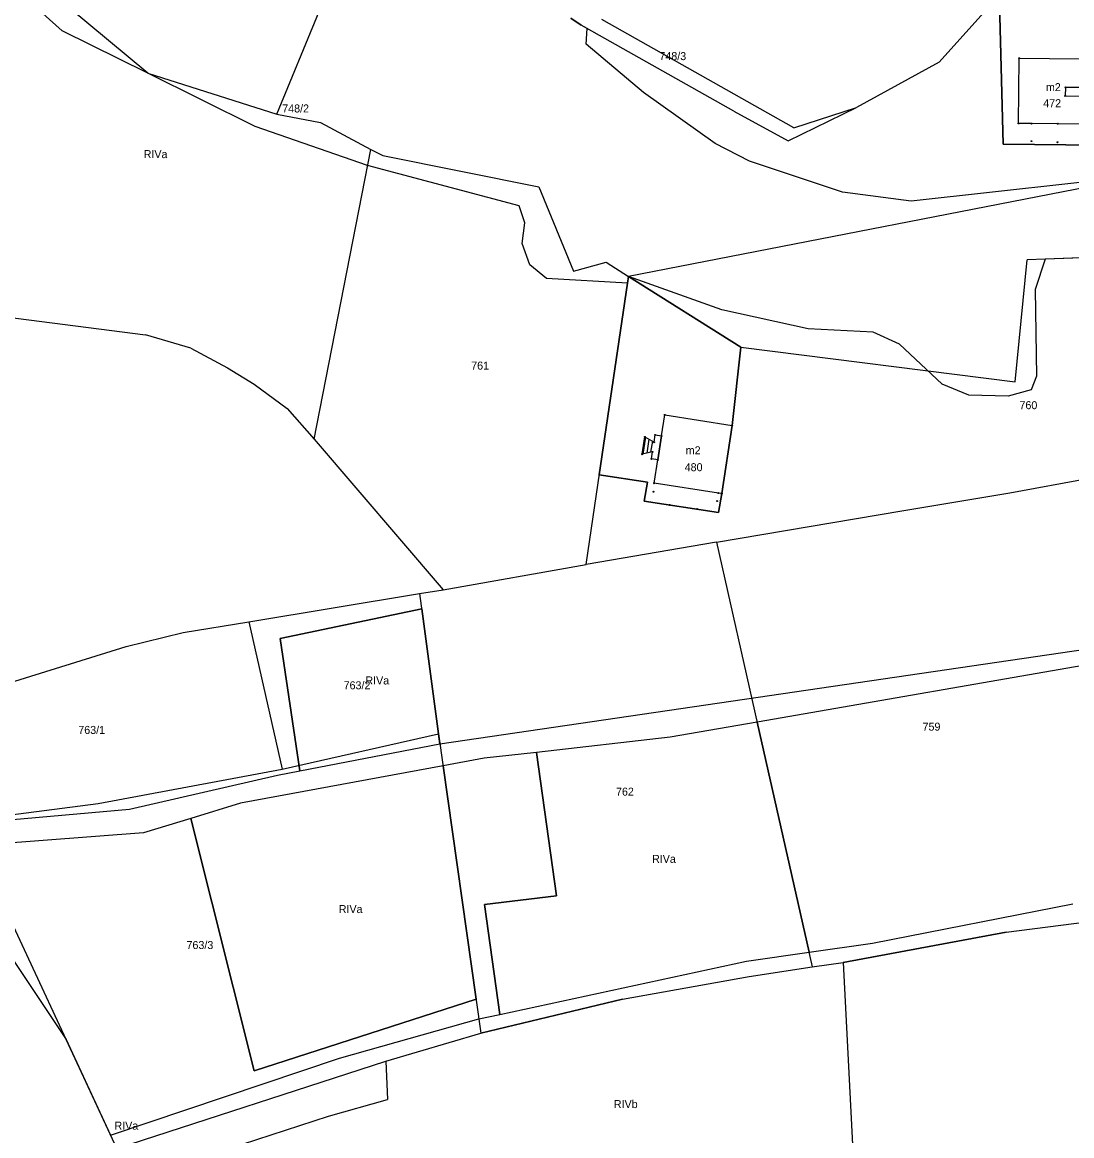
# Model space of a CAD drawing. Extents: x 7498273 to 7499989, y 5499795 to 5500810.
# Drawn here: x 7498697.1 to 7498893.9, y 5500193.5 to 5500402.3 of the extents above; entities that cross this region are included whole.
import ezdxf

# ---------------------------------------------------------------- set-up
doc = ezdxf.new("R2010")
doc.units = 0
for name, color, linetype in [('209-oznaczenie konturu klasyfikacyjnego', 7, 'Continuous'), ('211-numer działki ewidencyjnej', 7, 'Continuous'), ('217-kontur klasyfikacyjny', 7, 'Continuous'), ('218-kontur użytku gruntowego', 7, 'Continuous'), ('219-działka ewidencyjna', 7, 'Continuous'), ('312-budynek ewidencyjny', 7, 'Continuous'), ('312-oznaczenie budynku ewidencyjnego', 7, 'Continuous'), ('312-oznaczenie budynku ewidencyjnego-Atr117', 7, 'Continuous'), ('352-schody', 7, 'Continuous'), ('Punkt budynku', 7, 'Continuous')]:
    doc.layers.add(name, color=color, linetype=linetype)

# ---------------------------------------------------------------- blocks, each defined once
blk = doc.blocks.new('PUNKTBUD')
blk.add_circle((0, 0), 0.09)

msp = doc.modelspace()

# ---------------------------------------------------------------- linework, layer by layer
at = {"layer": '217-kontur klasyfikacyjny'}
for points in [[(7498704.59, 5500400.68), (7498692.57, 5500411.41)], [(7498881.05, 5500379.45), (7498880.27, 5500408.33)], [(7498801.93, 5500401.77), (7498799.95, 5500403.05)], [(7498720.65, 5500392.72), (7498704.59, 5500400.68)], [(7498803.06, 5500401.13), (7498801.93, 5500401.77)], [(7498802.86, 5500398.17), (7498803.06, 5500401.13)], [(7498813.6, 5500389.12), (7498802.86, 5500398.17)], [(7498740.78, 5500382.73), (7498720.65, 5500392.72)], [(7498827.05, 5500379.57), (7498813.6, 5500389.12)], [(7498761.84, 5500375.41), (7498740.78, 5500382.73)], [(7498833.45, 5500376.26), (7498827.05, 5500379.57)], [(7498898.64, 5500379.25), (7498881.05, 5500379.45)], [(7498850.89, 5500370.41), (7498833.45, 5500376.26)], [(7498790.29, 5500367.88), (7498761.84, 5500375.41)], [(7498908.98, 5500373.76), (7498863.81, 5500368.75)], [(7498863.81, 5500368.75), (7498850.89, 5500370.41)], [(7498791.33, 5500364.65), (7498790.29, 5500367.88)], [(7498790.87, 5500360.78), (7498791.33, 5500364.65)], [(7498792.29, 5500356.82), (7498790.87, 5500360.78)], [(7498795.4, 5500354.27), (7498792.29, 5500356.82)], [(7498888.92, 5500357.87), (7498887.03, 5500352.2)], [(7498902.28, 5500358.34), (7498888.92, 5500357.87)], [(7498810.57, 5500353.35), (7498810.76, 5500354.62)], [(7498828.29, 5500348.37), (7498810.76, 5500354.62)], [(7498810.76, 5500354.62), (7498831.84, 5500341.35)], [(7498810.57, 5500353.35), (7498795.4, 5500354.27)], [(7498805.31, 5500317.44), (7498810.57, 5500353.35)], [(7498887.03, 5500352.2), (7498887.26, 5500335.93)], [(7498844.5, 5500344.8), (7498828.29, 5500348.37)], [(7498856.66, 5500344.15), (7498844.5, 5500344.8)], [(7498861.61, 5500341.95), (7498856.66, 5500344.15)], [(7498831.84, 5500341.35), (7498830.25, 5500326.7)], [(7498869.61, 5500334.46), (7498861.61, 5500341.95)], [(7498887.26, 5500335.93), (7498886.31, 5500333.35)], [(7498874.57, 5500332.39), (7498869.61, 5500334.46)], [(7498881.95, 5500332.19), (7498874.57, 5500332.39)], [(7498886.31, 5500333.35), (7498881.95, 5500332.19)], [(7498830.25, 5500326.7), (7498828.26, 5500313.9)], [(7498814.33, 5500316.05), (7498805.31, 5500317.44)], [(7498813.71, 5500312.47), (7498814.33, 5500316.05)], [(7498828.26, 5500313.9), (7498827.64, 5500310.37)], [(7498827.64, 5500310.37), (7498813.71, 5500312.47)], [(7498745.47, 5500286.76), (7498772.01, 5500292.33)], [(7498772.01, 5500292.33), (7498775.16, 5500268.89)], [(7498775.42, 5500267.02), (7498925.02, 5500288.93)], [(7498749.18, 5500261.92), (7498745.47, 5500286.76)], [(7498900.34, 5500282.45), (7498834.9, 5500271.08)], [(7498834.9, 5500271.08), (7498818.61, 5500268.25)], [(7498844.63, 5500227.91), (7498834.9, 5500271.08)], [(7498749.18, 5500261.92), (7498775.42, 5500267.02)], [(7498775.16, 5500268.89), (7498775.42, 5500267.02)], [(7498818.61, 5500268.25), (7498793.52, 5500265.39)], [(7498793.52, 5500265.39), (7498783.73, 5500264.28)], [(7498797.28, 5500238.51), (7498793.52, 5500265.39)], [(7498776.01, 5500262.86), (7498738.05, 5500255.86)], [(7498783.73, 5500264.28), (7498776.01, 5500262.86)], [(7498776.01, 5500262.86), (7498782.2, 5500219.14)], [(7498717.23, 5500254.76), (7498745, 5500261.11)], [(7498745, 5500261.11), (7498749.18, 5500261.92)], [(7498672.71, 5500250.81), (7498717.23, 5500254.76)], [(7498738.05, 5500255.86), (7498728.72, 5500253)], [(7498728.72, 5500253), (7498719.84, 5500250.28)], [(7498740.6, 5500205.66), (7498728.72, 5500253)], [(7498719.84, 5500250.28), (7498682.16, 5500247.41)], [(7498783.76, 5500236.86), (7498797.28, 5500238.51)], [(7498786.64, 5500216.26), (7498783.76, 5500236.86)], [(7498856.53, 5500229.62), (7498894.08, 5500236.97)], [(7498881.57, 5500231.71), (7498904.55, 5500234.65)], [(7498851.03, 5500225.97), (7498881.57, 5500231.71)], [(7498844.63, 5500227.91), (7498856.53, 5500229.62)], [(7498694.7, 5500227.52), (7498705.34, 5500211.55)], [(7498832.92, 5500226.22), (7498844.63, 5500227.91)], [(7498786.64, 5500216.26), (7498832.92, 5500226.22)], [(7498833.4, 5500223.35), (7498845.25, 5500225.16)], [(7498845.25, 5500225.16), (7498851.03, 5500225.97)], [(7498809.65, 5500219.11), (7498833.4, 5500223.35)], [(7498782.2, 5500219.14), (7498740.6, 5500205.66)], [(7498783.11, 5500212.72), (7498809.65, 5500219.11)], [(7498756.62, 5500208.05), (7498782.73, 5500215.42)], [(7498782.73, 5500215.42), (7498786.64, 5500216.26)], [(7498765.31, 5500207.49), (7498783.11, 5500212.72)], [(7498705.34, 5500211.55), (7498713.67, 5500193.65)], [(7498713.67, 5500193.65), (7498756.62, 5500208.05)], [(7498714.83, 5500191.15), (7498765.31, 5500207.49)]]:
    msp.add_lwpolyline(points, dxfattribs=at)
at = {"layer": '218-kontur użytku gruntowego'}
for points in [[(7498704.59, 5500400.68), (7498692.57, 5500411.41)], [(7498880.27, 5500408.33), (7498881.05, 5500379.45)], [(7498801.93, 5500401.77), (7498799.95, 5500403.05)], [(7498720.65, 5500392.72), (7498704.59, 5500400.68)], [(7498803.06, 5500401.13), (7498801.93, 5500401.77)], [(7498802.86, 5500398.17), (7498803.06, 5500401.13)], [(7498813.6, 5500389.12), (7498802.86, 5500398.17)], [(7498740.78, 5500382.73), (7498720.65, 5500392.72)], [(7498827.05, 5500379.57), (7498813.6, 5500389.12)], [(7498761.84, 5500375.41), (7498740.78, 5500382.73)], [(7498833.45, 5500376.26), (7498827.05, 5500379.57)], [(7498881.05, 5500379.45), (7498898.64, 5500379.25)], [(7498850.89, 5500370.41), (7498833.45, 5500376.26)], [(7498790.29, 5500367.88), (7498761.84, 5500375.41)], [(7498908.98, 5500373.76), (7498863.81, 5500368.75)], [(7498863.81, 5500368.75), (7498850.89, 5500370.41)], [(7498791.33, 5500364.65), (7498790.29, 5500367.88)], [(7498790.87, 5500360.78), (7498791.33, 5500364.65)], [(7498792.29, 5500356.82), (7498790.87, 5500360.78)], [(7498795.4, 5500354.27), (7498792.29, 5500356.82)], [(7498888.92, 5500357.87), (7498887.03, 5500352.2)], [(7498902.28, 5500358.34), (7498888.92, 5500357.87)], [(7498810.76, 5500354.62), (7498810.57, 5500353.35)], [(7498831.84, 5500341.35), (7498810.76, 5500354.62)], [(7498828.29, 5500348.37), (7498810.76, 5500354.62)], [(7498810.57, 5500353.35), (7498795.4, 5500354.27)], [(7498810.57, 5500353.35), (7498805.31, 5500317.44)], [(7498887.03, 5500352.2), (7498887.26, 5500335.93)], [(7498844.5, 5500344.8), (7498828.29, 5500348.37)], [(7498856.66, 5500344.15), (7498844.5, 5500344.8)], [(7498861.61, 5500341.95), (7498856.66, 5500344.15)], [(7498830.25, 5500326.7), (7498831.84, 5500341.35)], [(7498869.61, 5500334.46), (7498861.61, 5500341.95)], [(7498887.26, 5500335.93), (7498886.31, 5500333.35)], [(7498874.57, 5500332.39), (7498869.61, 5500334.46)], [(7498881.95, 5500332.19), (7498874.57, 5500332.39)], [(7498886.31, 5500333.35), (7498881.95, 5500332.19)], [(7498828.26, 5500313.9), (7498830.25, 5500326.7)], [(7498805.31, 5500317.44), (7498814.33, 5500316.05)], [(7498814.33, 5500316.05), (7498813.71, 5500312.47)], [(7498827.64, 5500310.37), (7498828.26, 5500313.9)], [(7498813.71, 5500312.47), (7498827.64, 5500310.37)], [(7498772.01, 5500292.33), (7498745.47, 5500286.76)], [(7498775.16, 5500268.89), (7498772.01, 5500292.33)], [(7498775.42, 5500267.02), (7498925.02, 5500288.93)], [(7498745.47, 5500286.76), (7498749.18, 5500261.92)], [(7498900.34, 5500282.45), (7498834.9, 5500271.08)], [(7498834.9, 5500271.08), (7498818.61, 5500268.25)], [(7498834.9, 5500271.08), (7498844.63, 5500227.91)], [(7498749.18, 5500261.92), (7498775.42, 5500267.02)], [(7498775.42, 5500267.02), (7498775.16, 5500268.89)], [(7498818.61, 5500268.25), (7498793.52, 5500265.39)], [(7498793.52, 5500265.39), (7498783.73, 5500264.28)], [(7498793.52, 5500265.39), (7498797.28, 5500238.51)], [(7498776.01, 5500262.86), (7498738.05, 5500255.86)], [(7498783.73, 5500264.28), (7498776.01, 5500262.86)], [(7498782.2, 5500219.14), (7498776.01, 5500262.86)], [(7498717.23, 5500254.76), (7498745, 5500261.11)], [(7498745, 5500261.11), (7498749.18, 5500261.92)], [(7498672.71, 5500250.81), (7498717.23, 5500254.76)], [(7498738.05, 5500255.86), (7498728.72, 5500253)], [(7498728.72, 5500253), (7498719.84, 5500250.28)], [(7498728.72, 5500253), (7498740.6, 5500205.66)], [(7498719.84, 5500250.28), (7498682.16, 5500247.41)], [(7498797.28, 5500238.51), (7498783.76, 5500236.86)], [(7498783.76, 5500236.86), (7498786.64, 5500216.26)], [(7498856.53, 5500229.62), (7498894.08, 5500236.97)], [(7498881.57, 5500231.71), (7498904.55, 5500234.65)], [(7498851.03, 5500225.97), (7498881.57, 5500231.71)], [(7498844.63, 5500227.91), (7498856.53, 5500229.62)], [(7498694.7, 5500227.52), (7498705.34, 5500211.55)], [(7498832.92, 5500226.22), (7498844.63, 5500227.91)], [(7498786.64, 5500216.26), (7498832.92, 5500226.22)], [(7498833.4, 5500223.35), (7498845.25, 5500225.16)], [(7498845.25, 5500225.16), (7498851.03, 5500225.97)], [(7498809.65, 5500219.11), (7498833.4, 5500223.35)], [(7498740.6, 5500205.66), (7498782.2, 5500219.14)], [(7498783.11, 5500212.72), (7498809.65, 5500219.11)], [(7498756.62, 5500208.05), (7498782.73, 5500215.42)], [(7498782.73, 5500215.42), (7498786.64, 5500216.26)], [(7498765.31, 5500207.49), (7498783.11, 5500212.72)], [(7498705.34, 5500211.55), (7498713.67, 5500193.65)], [(7498713.67, 5500193.65), (7498756.62, 5500208.05)], [(7498714.83, 5500191.15), (7498765.31, 5500207.49)]]:
    msp.add_lwpolyline(points, dxfattribs=at)
at = {"layer": '219-działka ewidencyjna'}
for points in [[(7498720.65, 5500392.72), (7498698.56, 5500411.17)], [(7498744.86, 5500385.07), (7498752.79, 5500404.3)], [(7498799.95, 5500403.05), (7498801.93, 5500401.77)], [(7498841.78, 5500382.52), (7498805.77, 5500402.82)], [(7498869.05, 5500394.79), (7498877.42, 5500404.13)], [(7498830.51, 5500385.61), (7498801.93, 5500401.77)], [(7498869.05, 5500394.79), (7498853.55, 5500386.29)], [(7498720.65, 5500392.72), (7498744.86, 5500385.07)], [(7498840.7, 5500380.06), (7498853.55, 5500386.29)], [(7498841.78, 5500382.52), (7498853.55, 5500386.29)], [(7498744.86, 5500385.07), (7498753.01, 5500383.52)], [(7498830.51, 5500385.61), (7498840.7, 5500380.06)], [(7498753.01, 5500383.52), (7498762.44, 5500378.46)], [(7498751.82, 5500324.13), (7498762.44, 5500378.46)], [(7498762.44, 5500378.46), (7498764.71, 5500377.3)], [(7498764.71, 5500377.3), (7498794, 5500371.42)], [(7498908.98, 5500373.76), (7498810.76, 5500354.62)], [(7498794, 5500371.42), (7498800.47, 5500355.62)], [(7498800.47, 5500355.62), (7498806.58, 5500357.28)], [(7498806.58, 5500357.28), (7498810.76, 5500354.62)], [(7498883.29, 5500334.86), (7498885.55, 5500357.75)], [(7498906.19, 5500358.48), (7498885.55, 5500357.75)], [(7498802.84, 5500300.61), (7498810.76, 5500354.62)], [(7498831.84, 5500341.35), (7498810.76, 5500354.62)], [(7498676.4, 5500349.28), (7498720.2, 5500343.69)], [(7498728.74, 5500341.18), (7498720.2, 5500343.69)], [(7498728.74, 5500341.18), (7498735.6, 5500337.5)], [(7498831.84, 5500341.35), (7498883.29, 5500334.86)], [(7498735.6, 5500337.5), (7498740.57, 5500334.43)], [(7498740.57, 5500334.43), (7498746.8, 5500329.86)], [(7498746.8, 5500329.86), (7498751.82, 5500324.13)], [(7498751.82, 5500324.13), (7498776.05, 5500295.86)], [(7498882.27, 5500314.05), (7498897.24, 5500316.78)], [(7498862.02, 5500310.7), (7498882.27, 5500314.05)], [(7498827.29, 5500304.83), (7498862.02, 5500310.7)], [(7498827.29, 5500304.83), (7498802.84, 5500300.61)], [(7498827.29, 5500304.83), (7498845.25, 5500225.16)], [(7498776.05, 5500295.86), (7498802.84, 5500300.61)], [(7498739.57, 5500289.88), (7498771.62, 5500295.2)], [(7498771.62, 5500295.2), (7498776.05, 5500295.86)], [(7498771.62, 5500295.2), (7498775.16, 5500268.89)], [(7498727.28, 5500287.85), (7498739.57, 5500289.88)], [(7498739.57, 5500289.88), (7498745.87, 5500262.24)], [(7498716.61, 5500285.22), (7498727.28, 5500287.85)], [(7498669.36, 5500270.56), (7498716.61, 5500285.22)], [(7498745.87, 5500262.24), (7498775.16, 5500268.89)], [(7498775.16, 5500268.89), (7498783.11, 5500212.72)], [(7498711.32, 5500255.79), (7498745.87, 5500262.24)], [(7498672.71, 5500250.81), (7498711.32, 5500255.79)], [(7498714.83, 5500191.15), (7498689.24, 5500246.14)], [(7498881.57, 5500231.71), (7498904.55, 5500234.65)], [(7498881.57, 5500231.71), (7498851.03, 5500225.97)], [(7498833.4, 5500223.35), (7498845.25, 5500225.16)], [(7498845.25, 5500225.16), (7498851.03, 5500225.97)], [(7498851.03, 5500225.97), (7498853.17, 5500184.58)], [(7498809.65, 5500219.11), (7498833.4, 5500223.35)], [(7498809.65, 5500219.11), (7498783.11, 5500212.72)], [(7498765.31, 5500207.49), (7498783.11, 5500212.72)], [(7498714.83, 5500191.15), (7498765.31, 5500207.49)], [(7498765.31, 5500207.49), (7498765.58, 5500200.29)], [(7498754.55, 5500197.17), (7498765.58, 5500200.29)], [(7498738.38, 5500191.91), (7498754.55, 5500197.17)]]:
    msp.add_lwpolyline(points, dxfattribs=at)
at = {"layer": '312-budynek ewidencyjny'}
for points in [[(7498883.93, 5500383.32), (7498884.06, 5500395.55)], [(7498884.06, 5500395.55), (7498895.42, 5500395.45)], [(7498892.7, 5500390.08), (7498892.68, 5500388.48)], [(7498892.68, 5500388.48), (7498896.98, 5500388.44)], [(7498895.3, 5500390.06), (7498892.7, 5500390.08)], [(7498886.36, 5500383.3), (7498883.93, 5500383.32)], [(7498891.28, 5500383.25), (7498886.36, 5500383.3)], [(7498896.93, 5500383.19), (7498891.28, 5500383.25)], [(7498816.98, 5500324.72), (7498817.59, 5500328.65)], [(7498817.59, 5500328.65), (7498830.25, 5500326.7)], [(7498830.25, 5500326.7), (7498828.26, 5500313.9)], [(7498816.29, 5500320.24), (7498816.98, 5500324.72)], [(7498815.61, 5500315.85), (7498816.29, 5500320.24)], [(7498827.63, 5500314), (7498815.61, 5500315.85)], [(7498828.26, 5500313.9), (7498827.63, 5500314)]]:
    msp.add_lwpolyline(points, dxfattribs=at)
at = {"layer": '352-schody'}
msp.add_lwpolyline([(7498815.57, 5500323.54), (7498815.77, 5500324.91), (7498816.98, 5500324.72), (7498816.29, 5500320.24), (7498815.1, 5500320.42), (7498815.3, 5500321.74), (7498813.37, 5500321.3), (7498813.87, 5500324.53)], close=True, dxfattribs=at)
msp.add_lwpolyline([(7498815.57, 5500323.54), (7498815.77, 5500324.91), (7498816.98, 5500324.72), (7498816.29, 5500320.24), (7498815.1, 5500320.42), (7498815.3, 5500321.74), (7498813.37, 5500321.3), (7498813.87, 5500324.53)], close=True, dxfattribs=at)
for points in [[(7498813.953, 5500324.481), (7498813.467, 5500321.322)], [(7498814.603, 5500324.103), (7498814.201, 5500321.49)], [(7498815.253, 5500323.724), (7498814.935, 5500321.657)]]:
    msp.add_lwpolyline(points, dxfattribs=at)

# ---------------------------------------------------------------- block references
at = {"layer": 'Punkt budynku'}
for p in [(7498884.06, 5500395.55), (7498892.7, 5500390.08), (7498892.68, 5500388.48), (7498883.93, 5500383.32), (7498886.36, 5500383.3), (7498891.28, 5500383.25), (7498886.32, 5500379.99), (7498891.25, 5500379.78), (7498817.59, 5500328.65), (7498830.25, 5500326.7), (7498813.87, 5500324.53), (7498815.57, 5500323.54), (7498815.77, 5500324.91), (7498816.98, 5500324.72), (7498813.37, 5500321.3), (7498815.3, 5500321.74), (7498815.1, 5500320.42), (7498816.29, 5500320.24), (7498815.61, 5500315.85), (7498815.47, 5500314.25), (7498827.63, 5500314), (7498828.26, 5500313.9), (7498818.49, 5500311.78), (7498823.65, 5500311.01), (7498827.4, 5500312.51)]:
    msp.add_blockref('PUNKTBUD', p, dxfattribs=at)

# ---------------------------------------------------------------- texts
at = {"layer": '209-oznaczenie konturu klasyfikacyjnego'}
for s, p in [('RIVa', (7498719.88, 5500376.81)), ('RIVa', (7498761.45, 5500278.13)), ('RIVa', (7498815.2, 5500244.67)), ('RIVa', (7498756.46, 5500235.26)), ('RIVb', (7498808.04, 5500198.7)), ('RIVa', (7498714.41, 5500194.65))]:
    msp.add_text(s, height=1.5, dxfattribs=at).set_placement(p)
at = {"layer": '211-numer działki ewidencyjnej'}
for s, p in [('748/3', (7498816.58, 5500395.19)), ('748/2', (7498745.86, 5500385.37)), ('761', (7498781.29, 5500337.16)), ('760', (7498884.09, 5500329.74)), ('763/2', (7498757.37, 5500277.22)), ('763/1', (7498707.62, 5500268.85)), ('759', (7498865.92, 5500269.47)), ('762', (7498808.44, 5500257.28)), ('763/3', (7498727.91, 5500228.52))]:
    msp.add_text(s, height=1.5, dxfattribs=at).set_placement(p)
at = {"layer": '312-oznaczenie budynku ewidencyjnego'}
for s, p in [('472', (7498888.55, 5500386.36)), ('480', (7498821.32, 5500318.11))]:
    msp.add_text(s, height=1.5, dxfattribs=at).set_placement(p)
at = {"layer": '312-oznaczenie budynku ewidencyjnego-Atr117'}
for p in [(7498889.046, 5500389.37), (7498821.516, 5500321.28)]:
    msp.add_text('m2', height=1.5, dxfattribs=at).set_placement(p)

doc.saveas('drawing.dxf')
